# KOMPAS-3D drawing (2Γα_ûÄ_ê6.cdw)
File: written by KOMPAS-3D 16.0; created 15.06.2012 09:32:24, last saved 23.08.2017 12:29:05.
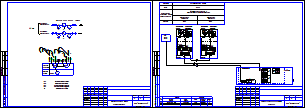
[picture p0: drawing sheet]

Sheets 1-2: A3, landscape

Title block, sheet 1: name: Руководство по эксплуатации; sheet number: 1; sheets: 27; organisation: ООО"Интелприбор"; sheet format: A3; stored path: W:\Users\smirnov_v\Desktop\шаблоны\4-х трубка\4-х трубка ГВС-max.cdw / D:\Проекты\Лыткарино\ул. Квартал 3А, д.25\710.74 РП.cdw; file name: 4-х трубка ГВС-max.cdw / 710.74 РП.cdw; cell 51: МО, Воскресенсикй р-н, п. Хорлово, ул. Интернациональная, д. 4; cell 320: Р
Title block, sheet 2: sheet number: 2

Views: Вид 2, Вид 3
Referenced files in C:\Program Files (x86)\ASCON\KOMPAS-3D V16\Sys\: spds.lcs, EngSys.lcs, GRAPHIC.LHS
Referenced files: graphic.tdp
Referenced files in W:\Users\smirnov_v\Desktop\шаблоны\4-х трубка\: 4-х трубка ГВС-max.cdw
Referenced files in D:\Проекты\Лыткарино\ул. Квартал 3А, д.25\: 710.74 РП.cdw
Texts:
  Смирнов В.С.
  УУ-3423
  GOST Common
  Normal
  List Paragraph
  heading 3
  для схемы
  txt
  Т0-элементы
  ВРУ
  Плата подключений
  СБ МКТС
  UP+
  UP-
  ИМП
  Лин
  Измерительный
  модуль М121
  Pt 100
  Преобразователь
  температуры
  давления
  каб.
  Начало
  трассы
  Трассы
  Марка
  Проложен
  Изм. модуль (Т1)
  Изм. модуль (Т2)
  ВРУ 220В, 50 Гц
  ИМ (Т1)
  FTP
  ПВС
  Конец
  Кол-во и
  сеч. жил
  Длина,
  Преобразователь расхода
  Термопреобразователь
  Преобразователь давления
  Преобразователь цифровой
  Системный блок МКТС
  приборы
  по месту
  шкаф
  учета
  UQIES
  Подающий
  трубопровод
  Обратный
  УУТЭ
  Функциональная схема
  Агрегат
  Системный блок  МКТС
  Среда
  Вода
  параметра и место
  отбора импульса
  Учет тепловой энергии и
  теплоносителя системы отопления
  отопления
  ИМ1
  ИМ2
  Размеры, параметризация
  сит. план
  подача ГВС
  обратка ГВС
  хвс
  обратка
  POLYLINE_STYLE_0.25_RGB_0_0_0
  стены
  Основная (не является границей для штриховки)
  POLYLINE_STYLE_0.18_RGB_0_0_0
  ХВС
  зеленая
  Красная тонкая
  арматура
  Подача
  Скрытая линия
  Ось Z
  Ось Y
  Ось X
  Образующая трубопровода (проектируемого)
  Трубопровод толщиной 0.6мм (одна линия)
  Трубопровод толщиной 1.2мм (одна линия)
  Трубопровод толщиной 1.0мм (одна линия)
  Трубопровод толщиной 0.8мм (одна линия)
  Трубопровод существующий (одна линия)
  Трубопровод невидимый (одна линия)
  Трубопровод демонтируемый (одна линия)
  Осевая трубопровода
  Осевая трубопровода (демонтируемого)
  Образующая трубопровода (существующего)
  Образующая трубопровода (невидимого)
  Изолированный трубопровод проектируемый (одна линия)
  Изолированный трубопровод существующий (одна линия)
  Образующая изоляции
  Изоляция
  Изолированный трубопровод невидимый (одна линия)
  Штрих пвс 075
  штрих пвс 2,5
  существующее оборудование
  Существующее оборудование
  K5LT_BASIC_RGB_0_0_255_THICK_0.53
  POLYLINE_STYLE_1.51_RGB_0_0_255
  POLYLINE_STYLE_0.50_RGB_128_128_128
  K5LT_AXLED_RGB_255_128_0_SC_1_THICK_0.18
  ACAD_ISO04W100_RGB_0_0_0_SC_1_THICK_0.18
  тонкая черная
  тонкая красная
  тонкая синяя
  тонкая оранж
  красн штрих
  пломбировка
  Провода
  синий штрих
  Стили документа
  G2co
  расход вторичной воды объемный
  расход вторичной воды объемный при 70гр
  Gco
  расход теплоносителя массовый
  расход теплоносит объемн подающ
  расход теплоносит объемн обр
  Лапир
  Ghvs
  Im1
  Im2
  Im3
  Im4
  Im5
  Khvs
  норматив ХВС
  число подъездов
  число этажей
  Nkv
  число квартир
  тепловая нагрузка на отопление
  сумма Q
  Qgvs
  тепловая нагрузка ГВС
  тепловая нагрузка на циркуляцию ГВС
  иммитовставка или под манометр
  ro1
  ro2
  ro3
  ro4
  верх предел темп граф
  нижн предел темп граф
  темп подачи ГВС
  темп обр ГВС
  темр хол воды
  vzdh
  Kchn
  Ktp
  Knp
  tnv
  Vклап
  KLP
  RPD
  RDS
  PUMP
  ro5
  beta
  tnv98
  Shifr
  Переход ГОСТ 17378-2001
  Переход
  ГОСТ
  Сталь 09Г2С ГОСТ 19281-89
  Втулка 20x50
  Лит-Масса-Масштаб
  Материал-Предприятие
  Title Specification
  Body Specification ( left align )
  Body Specificaton ( centered )
  Поз.
  Кол.
  Приме-
  чание
  Таблица спецификации
  Засыпка
  Штрих3
  Штрих2
  Штрих1
  Песок
  Штр0.5пр7
  Штр0.5пр12
  Штр0.3пр10
  Штр1.4пр21.21
  Штр1пр15
  Штр2.12пр35
  Штр1.5пр25
  Штр2.82пр42.42
  Штр2пр30
  SACNCR_ISO 1
  Электрощитовая
  Пр-1
  Ок-1
  Обозначение стандарта
  Типоразмер
  Пояснительная записка
  автоматизации
  Рабочие чертежи основного комплекта. ГОСТ Р 21.1101-2009 Ф3
  Стадия
  Лист
  Листов
  Изм.
  Кол.уч.
  №док.
  Подп.
  Дата
  Разраб.
  Пров.
  Т.контр.
  Н.контр.
  Утв.
  Изменение
  Номер документа
  Подпись
  Наименование объекта строительства, в состав которого входит здание, наим. микр
  Наименование здания (сооружения)
  Порядковый номер листа
  Количество листов в документе
  Наименование изображения
  Индекс предприятия, выпускающего документ
  Инв. № подл.
  Подп. и дата
  Взам. инв. №
  Инвентарный номер подлинника
  Подпись принявшего подлинник на хранение
  Инвентарный номер подлинника, взамен которого выпущен данный подлинник
  Согласовано
  Формат листа
  Согласование
  03 Рабочие чертежи основного комплекта. ГОСТ Р 21.1101-2009 Ф3
  Схема соединений внешних
  проводок
Dimensions and other numbers on the sheet: 220В; 50Гц; 1; 2; 3; 6; 5; 4; 4-20; 2x2x0,52; 3х0,75; 50; 9; 1,2; 3,4; 5,6; 7,8; 10; 7; 8; 5,0; 3,2388; 0,0400; 40; 95; 3,1876; 4,5; 70; 09Г2С; 20; 27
